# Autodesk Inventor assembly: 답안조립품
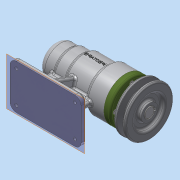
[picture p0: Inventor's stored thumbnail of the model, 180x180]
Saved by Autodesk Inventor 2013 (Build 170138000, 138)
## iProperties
Created: 2016-06
Part Number: 답안조립품
Document SubType Name: Assembly
Designer: dgall
Author: dgall
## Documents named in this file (12)
- C:\Users\dgall\Desktop\460607v1024\답안조립품.iam
- C:\Users\dgall\Desktop\460607v1024\V벨트풀리.ipt
- C:\Users\dgall\Desktop\460607v1024\멈춤나사 M3x8.ipt
- C:\Users\dgall\Desktop\460607v1024\베어링 6004.ipt
- C:\Users\dgall\Desktop\460607v1024\베어링 51202.ipt
- C:\Users\dgall\Desktop\460607v1024\본체.ipt
- C:\Users\dgall\Desktop\460607v1024\볼트 M4 x 12.ipt
- C:\Users\dgall\Desktop\460607v1024\어댑터슬리브.ipt
- C:\Users\dgall\Desktop\460607v1024\오일 실.ipt
- C:\Users\dgall\Desktop\460607v1024\축.ipt
- C:\Users\dgall\Desktop\460607v1024\커버.ipt
- C:\Users\dgall\Desktop\460607v1024\키 5 x 5 x 16.ipt
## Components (6 placed, 2 different names)
1. V벨트풀리:1 — 플러쉬:1
2. ISO 4762 M4 x 12:1
3. ISO 4762 M4 x 12:2
4. ISO 4762 M4 x 12:3
5. ISO 4762 M4 x 12:4
6. ISO 4762 M4 x 12:5
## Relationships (1: Flush 1)
- 플러쉬:1 [Flush]: V벨트풀리:1
